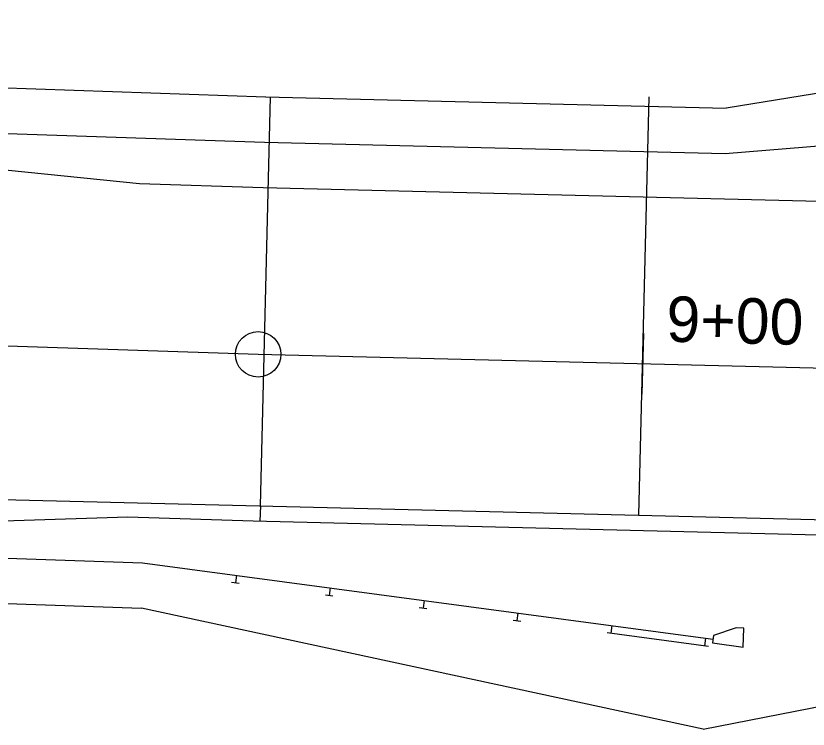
# Model space of a CAD drawing. Extents: x 2191309 to 2193046, y 863659 to 865133.
# Drawn here: x 2191776.6 to 2191828.9, y 865058.9 to 865105.9 of the extents above; entities that cross this region are included whole.
import ezdxf

# ---------------------------------------------------------------- set-up
doc = ezdxf.new("R2010")
doc.units = 0
for name, color, linetype in [('D_Guardrail_Beam_Lt', 7, 'Continuous'), ('D_Guardrail_Beam_Rt', 7, 'Continuous'), ('D_Guardrail_End_MidSplice', 7, 'Continuous'), ('D_Roadway_Centerline', 7, 'Continuous'), ('D_Roadway_Centerline_Flags', 7, 'Continuous'), ('D_Roadway_Centerline_Text', 7, 'Continuous'), ('D_Roadway_Edge_Shoulder', 7, 'Continuous'), ('D_Roadway_Edge_TW', 7, 'Continuous'), ('JUNK', 7, 'Continuous')]:
    doc.layers.add(name, color=color, linetype=linetype)

msp = doc.modelspace()

# ---------------------------------------------------------------- linework, layer by layer
at = {"layer": 'D_Guardrail_Beam_Lt'}
for p, q in [((2191764.105, 865098.579), (2191793.049, 865097.585)), ((2191793.049, 865097.585), (2191823.454, 865096.839))]:
    msp.add_line(p, q, dxfattribs=at)
at = {"layer": 'D_Guardrail_Beam_Rt'}
msp.add_line((2191763.145, 865070.595), (2191785.007, 865069.845), dxfattribs=at)
at = {"layer": 'D_Guardrail_End_MidSplice'}
for p, q in [((2191823.454, 865096.839), (2191860.827, 865099.923)), ((2191785.007, 865069.845), (2191822.174, 865064.861)), ((2191791.202, 865069.014), (2191791.135, 865068.519)), ((2191790.887, 865068.552), (2191791.383, 865068.485)), ((2191797.396, 865068.184), (2191797.33, 865067.688)), ((2191797.082, 865067.721), (2191797.577, 865067.655)), ((2191803.591, 865067.353), (2191803.524, 865066.857)), ((2191803.276, 865066.891), (2191803.772, 865066.824)), ((2191809.785, 865066.522), (2191809.719, 865066.027)), ((2191809.471, 865066.06), (2191809.967, 865065.993)), ((2191815.98, 865065.691), (2191815.913, 865065.196)), ((2191824.193, 865065.538), (2191822.703, 865065.042)), ((2191824.693, 865065.525), (2191824.193, 865065.538)), ((2191824.66, 865064.275), (2191824.693, 865065.525)), ((2191815.666, 865065.229), (2191822.356, 865064.332)), ((2191815.666, 865065.229), (2191816.161, 865065.163)), ((2191822.703, 865065.042), (2191822.637, 865064.547)), ((2191822.174, 865064.861), (2191822.108, 865064.365)), ((2191822.174, 865064.861), (2191822.67, 865064.794)), ((2191822.637, 865064.547), (2191824.66, 865064.275)), ((2191821.86, 865064.398), (2191822.356, 865064.332))]:
    msp.add_line(p, q, dxfattribs=at)
at = {"layer": 'D_Roadway_Centerline'}
for p, q in [((2191489.641, 865093.991), (2191792.637, 865083.591)), ((2191792.637, 865083.591), (2191929.724, 865080.226))]:
    msp.add_line(p, q, dxfattribs=at)
at = {"layer": 'D_Roadway_Centerline_Flags'}
msp.add_circle((2191792.637, 865083.591), 1.5, dxfattribs=at)
at = {"layer": 'D_Roadway_Centerline_Text'}
msp.add_lwpolyline([(2191818.069, 865084.968), (2191817.971, 865080.969)], dxfattribs=at)
at = {"layer": 'D_Roadway_Edge_Shoulder'}
for p, q in [((2191860.974, 865105.922), (2191823.528, 865099.838)), ((2191735.145, 865102.575), (2191793.152, 865100.584)), ((2191793.123, 865100.585), (2191823.528, 865099.838)), ((2191792.782, 865073.585), (2191792.757, 865072.585)), ((2191733.979, 865068.595), (2191784.928, 865066.846)), ((2191822.016, 865058.863), (2191784.928, 865066.846))]:
    msp.add_line(p, q, dxfattribs=at)
for points in [[(2191792.961, 865094.587), (2191893.267, 865092.124), (2191918.276, 865092.192)], [(2191767.459, 865067.445), (2191767.691, 865074.201), (2191867.759, 865071.744), (2191867.662, 865067.782)], [(2191792.314, 865072.596), (2191892.727, 865070.131), (2191917.703, 865068.829)], [(2191822.016, 865058.863), (2191867.662, 865067.782), (2191902.756, 865066.856), (2191917.639, 865066.342)]]:
    msp.add_lwpolyline(points, dxfattribs=at)
at = {"layer": 'D_Roadway_Edge_TW'}
for points in [[(2191735.053, 865099.909), (2191784.798, 865094.867), (2191792.961, 865094.587)], [(2191734.07, 865071.26), (2191784.044, 865072.88), (2191792.314, 865072.596)]]:
    msp.add_lwpolyline(points, dxfattribs=at)
at = {"layer": 'JUNK'}
for p, q in [((2191792.782, 865073.585), (2191793.445, 865100.577)), ((2191817.774, 865072.971), (2191818.452, 865100.584))]:
    msp.add_line(p, q, dxfattribs=at)

# ---------------------------------------------------------------- texts
at = {"layer": 'D_Roadway_Centerline_Text'}
msp.add_text('9+00', height=3, rotation=358.5937, dxfattribs=at).set_placement((2191819.556, 865084.431))

doc.saveas('drawing.dxf')
